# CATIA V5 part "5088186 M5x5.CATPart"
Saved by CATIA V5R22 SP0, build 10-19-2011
Part number: 5088186 M5x5
Property "ParasolidId": 18
Property "PSOL_INSTNR": 6
Property "ParasolidId": 15
Property "PSOL_INSTNR": 6
Bounding box of the stored display mesh (mm): x -2.378 to 2.378, y -5 to 0, z -2.5 to 2.5
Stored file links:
  U:\S9A\PER\CAO\Assemblage\Cadre\Chariot_Y\Prehenseur\5088186 M5x5.CATPart
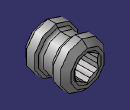
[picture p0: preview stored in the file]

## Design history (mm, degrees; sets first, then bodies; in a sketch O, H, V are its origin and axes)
Body1 "5088186 M5x5" (main body)
  Solid1: solid without history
